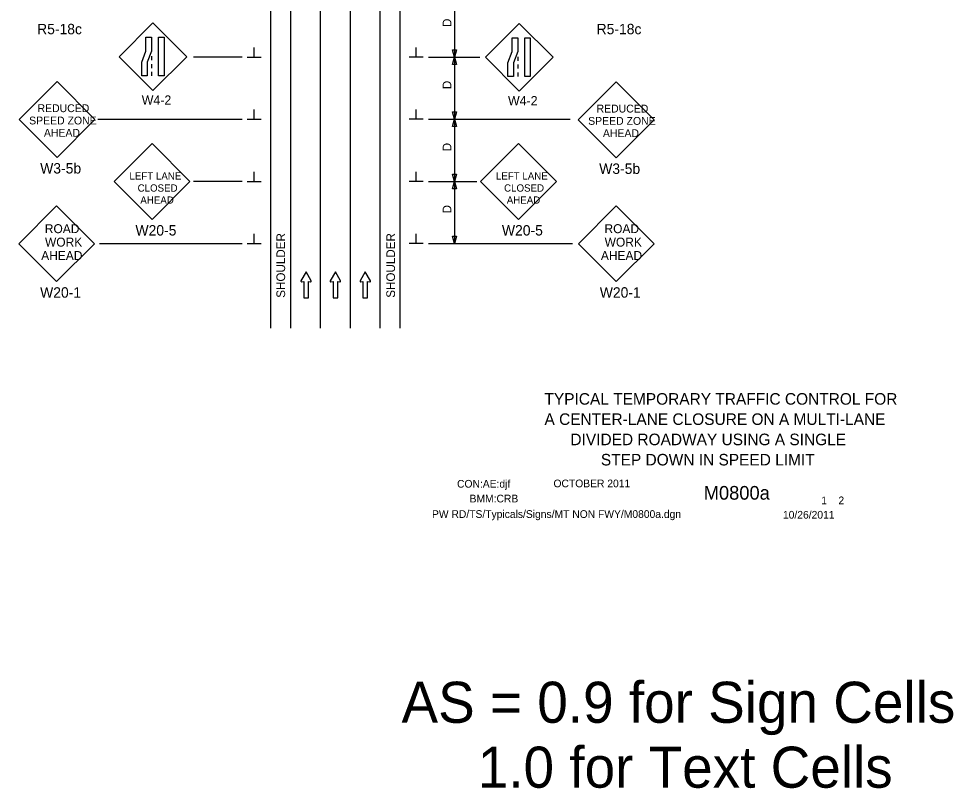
# Model space of a CAD drawing. Extents: x 16732 to 18482, y 5716 to 6919.
# Drawn here: x 16738 to 17490, y 5716 to 6335 of the extents above; entities that cross this region are included whole.
import ezdxf

# ---------------------------------------------------------------- set-up
doc = ezdxf.new("R2010")
doc.units = 0
for name, color, linetype in [('ALI_LEGAL_EX', 7, 'Continuous'), ('BORDER', 7, 'Continuous'), ('BORDER_SIGNAL_WO', 7, 'Continuous'), ('MT_SCRATCH_LEVEL_E', 7, 'Continuous'), ('PAVT_EDGE_EX', 7, 'Continuous'), ('TRAFFIC_SIGNS_PR', 7, 'Continuous'), ('TYPICAL_TEXT_DIMEN_PR', 7, 'Continuous')]:
    doc.layers.add(name, color=color, linetype=linetype)

msp = doc.modelspace()

# ---------------------------------------------------------------- linework, layer by layer
at = {"layer": 'ALI_LEGAL_EX'}
for p, q in [((16980.68, 6904.41), (16980.68, 6086.27)), ((17004.68, 6904.41), (17004.68, 6086.27))]:
    msp.add_line(p, q, dxfattribs=at)
for points in [[(16980.68, 6304.41), (16980.68, 6279.41)], [(17004.68, 6304.41), (17004.68, 6279.41)], [(16980.68, 6204.41), (16980.68, 6179.41)], [(17004.68, 6204.41), (17004.68, 6179.41)], [(16980.68, 6104.41), (16980.68, 6086.27)], [(17004.68, 6104.41), (17004.68, 6086.27)]]:
    msp.add_lwpolyline(points, dxfattribs=at)
at = {"layer": 'MT_SCRATCH_LEVEL_E'}
for p, q in [((16969.24, 6131.56), (16965.12, 6124.32)), ((16973.38, 6124.32), (16969.24, 6131.56)), ((16992.78, 6131.56), (16988.67, 6124.32)), ((16996.93, 6124.32), (16992.78, 6131.56)), ((17016.85, 6131.56), (17012.74, 6124.32)), ((17021, 6124.32), (17016.85, 6131.56)), ((16965.61, 6123.63), (16967.38, 6123.95)), ((16967.38, 6123.95), (16967.38, 6110.69)), ((16971.13, 6110.69), (16971.13, 6123.95)), ((16971.13, 6123.95), (16972.9, 6123.63)), ((16989.15, 6123.63), (16990.93, 6123.95)), ((16990.93, 6123.95), (16990.93, 6110.69)), ((16994.67, 6110.69), (16994.67, 6123.95)), ((16994.67, 6123.95), (16996.45, 6123.63)), ((17013.22, 6123.63), (17015, 6123.95)), ((17015, 6123.95), (17015, 6110.69)), ((17018.74, 6110.69), (17018.74, 6123.95)), ((17018.74, 6123.95), (17020.52, 6123.63)), ((16967.38, 6110.69), (16971.13, 6110.69)), ((16990.93, 6110.69), (16994.67, 6110.69)), ((17015, 6110.69), (17018.74, 6110.69))]:
    msp.add_line(p, q, dxfattribs=at)
for centre, start, end in [((16965.53, 6124.09), 150.42484, 279.96381), ((16972.97, 6124.09), 260.03619, 29.77312), ((16989.08, 6124.09), 150.42484, 279.96381), ((16996.52, 6124.09), 260.03619, 29.77312), ((17013.15, 6124.09), 150.42484, 279.96381), ((17020.59, 6124.09), 260.03619, 29.77312)]:
    msp.add_arc(centre, 0.463, start, end, dxfattribs=at)
at = {"layer": 'PAVT_EDGE_EX'}
for p, q in [((16940.68, 6904.41), (16940.68, 6086.27)), ((16956.68, 6904.41), (16956.68, 6086.27)), ((17028.68, 6904.41), (17028.68, 6086.27)), ((17044.68, 6904.41), (17044.68, 6086.27))]:
    msp.add_line(p, q, dxfattribs=at)
at = {"layer": 'TRAFFIC_SIGNS_PR'}
for p, q in [((16846.05, 6331.9), (16818.89, 6304.75)), ((16873.2, 6304.75), (16846.05, 6331.9)), ((17140.75, 6331.41), (17113.6, 6304.25)), ((17167.91, 6304.25), (17140.75, 6331.41)), ((16818.89, 6304.75), (16846.05, 6277.6)), ((16844.8, 6305.24), (16844.8, 6302.04)), ((16846.05, 6277.6), (16873.2, 6304.75)), ((17113.6, 6304.25), (17140.75, 6277.1)), ((17139.51, 6304.75), (17139.51, 6301.55)), ((17140.75, 6277.1), (17167.91, 6304.25)), ((16844.8, 6298.84), (16844.8, 6295.64)), ((17139.51, 6298.35), (17139.51, 6295.15)), ((16844.8, 6292.44), (16844.8, 6289.24)), ((17139.51, 6291.95), (17139.51, 6288.75)), ((16768.84, 6284.73), (16738.29, 6254.19)), ((16799.38, 6254.19), (16768.84, 6284.73)), ((17218.65, 6284.42), (17188.1, 6253.88)), ((17249.19, 6253.88), (17218.65, 6284.42)), ((16738.29, 6254.19), (16768.84, 6223.64)), ((16768.84, 6223.64), (16799.38, 6254.19)), ((17188.1, 6253.88), (17218.65, 6223.33)), ((17218.65, 6223.33), (17249.19, 6253.88)), ((16845.25, 6234.84), (16814.7, 6204.29)), ((16875.79, 6204.29), (16845.25, 6234.84)), ((17140.11, 6234.84), (17109.56, 6204.29)), ((17170.65, 6204.29), (17140.11, 6234.84)), ((16814.7, 6204.29), (16845.25, 6173.74)), ((16845.25, 6173.74), (16875.79, 6204.29)), ((17109.56, 6204.29), (17140.11, 6173.74)), ((17140.11, 6173.74), (17170.65, 6204.29)), ((16768.53, 6184.86), (16737.99, 6154.32)), ((16799.08, 6154.32), (16768.53, 6184.86)), ((17218.85, 6184.86), (17188.31, 6154.32)), ((17249.4, 6154.32), (17218.85, 6184.86)), ((16737.99, 6154.32), (16768.53, 6123.77)), ((16768.53, 6123.77), (16799.08, 6154.32)), ((17188.31, 6154.32), (17218.85, 6123.77)), ((17218.85, 6123.77), (17249.4, 6154.32))]:
    msp.add_line(p, q, dxfattribs=at)
for points in [[(16844.8, 6320.48), (16844.8, 6309.3), (16841.46, 6300.42), (16841.46, 6289.24), (16836.96, 6289.24), (16836.96, 6300.42), (16840.31, 6309.3), (16840.31, 6320.48)], [(16854.94, 6320.48), (16854.94, 6289.24), (16850.44, 6289.24), (16850.44, 6320.48)], [(17139.51, 6319.99), (17139.51, 6308.81), (17136.16, 6299.93), (17136.16, 6288.75), (17131.67, 6288.75), (17131.67, 6299.93), (17135.01, 6308.81), (17135.01, 6319.99)], [(17149.64, 6319.99), (17149.64, 6288.75), (17145.15, 6288.75), (17145.15, 6319.99)]]:
    msp.add_lwpolyline(points, close=True, dxfattribs=at)
at = {"layer": 'TYPICAL_TEXT_DIMEN_PR'}
for p, q in [((17088.68, 6354.43), (17088.68, 6304.43)), ((16927.55, 6304.43), (16927.55, 6312.21)), ((17057.8, 6304.43), (17057.8, 6312.21)), ((17088.68, 6304.43), (17087.11, 6310.29)), ((17087.11, 6310.29), (17088.68, 6310.29)), ((17088.68, 6310.29), (17090.25, 6310.29)), ((17090.25, 6310.29), (17088.68, 6304.43)), ((16917.68, 6304.43), (16878.68, 6304.43)), ((16921.93, 6304.43), (16933.18, 6304.43)), ((17063.43, 6304.43), (17052.18, 6304.43)), ((17067.68, 6304.43), (17109.12, 6304.43)), ((17087.11, 6298.57), (17088.68, 6304.43)), ((17088.68, 6304.43), (17088.68, 6254.43)), ((17088.68, 6304.43), (17090.25, 6298.57)), ((17088.68, 6298.57), (17087.11, 6298.57)), ((17090.25, 6298.57), (17088.68, 6298.57)), ((16927.55, 6254.43), (16927.55, 6262.21)), ((17057.8, 6254.43), (17057.8, 6262.21)), ((17088.68, 6254.43), (17087.11, 6260.29)), ((17087.11, 6260.29), (17088.68, 6260.29)), ((17088.68, 6260.29), (17090.25, 6260.29)), ((17090.25, 6260.29), (17088.68, 6254.43)), ((16801.71, 6254.43), (16917.68, 6254.43)), ((16921.93, 6254.43), (16933.18, 6254.43)), ((17063.43, 6254.43), (17052.18, 6254.43)), ((17067.68, 6254.43), (17181.75, 6254.43)), ((17087.11, 6248.57), (17088.68, 6254.43)), ((17088.68, 6254.43), (17088.68, 6204.43)), ((17088.68, 6254.43), (17090.25, 6248.57)), ((17088.68, 6248.57), (17087.11, 6248.57)), ((17090.25, 6248.57), (17088.68, 6248.57)), ((16927.55, 6204.43), (16927.55, 6212.21)), ((17057.8, 6204.43), (17057.8, 6212.21)), ((16917.68, 6204.43), (16878.68, 6204.43)), ((16921.93, 6204.43), (16933.18, 6204.43)), ((17063.43, 6204.43), (17052.18, 6204.43)), ((17067.68, 6204.43), (17106.68, 6204.43)), ((17088.68, 6204.43), (17087.11, 6210.29)), ((17087.11, 6210.29), (17088.68, 6210.29)), ((17087.11, 6198.57), (17088.68, 6204.43)), ((17088.68, 6210.29), (17090.25, 6210.29)), ((17090.25, 6210.29), (17088.68, 6204.43)), ((17088.68, 6204.43), (17088.68, 6154.43)), ((17088.68, 6204.43), (17090.25, 6198.57)), ((17088.68, 6198.57), (17087.11, 6198.57)), ((17090.25, 6198.57), (17088.68, 6198.57)), ((16927.55, 6154.43), (16927.55, 6162.21)), ((17057.8, 6154.43), (17057.8, 6162.21)), ((17088.68, 6154.43), (17087.11, 6160.29)), ((17087.11, 6160.29), (17088.68, 6160.29)), ((17088.68, 6160.29), (17090.25, 6160.29)), ((17090.25, 6160.29), (17088.68, 6154.43)), ((16802.89, 6154.43), (16917.68, 6154.43)), ((16921.93, 6154.43), (16933.18, 6154.43)), ((17063.43, 6154.43), (17052.18, 6154.43)), ((17067.68, 6154.43), (17183.65, 6154.43))]:
    msp.add_line(p, q, dxfattribs=at)

# ---------------------------------------------------------------- texts
at = {"layer": 'BORDER'}
for s, p in [('TYPICAL TEMPORARY TRAFFIC CONTROL FOR', (17161.04, 6024.8)), ('A CENTER-LANE CLOSURE ON A MULTI-LANE', (17161.06, 6008.5)), ('DIVIDED ROADWAY USING A SINGLE ', (17181.92, 5992.2)), ('STEP DOWN IN SPEED LIMIT', (17206.42, 5975.9))]:
    msp.add_text(s, height=9.3, dxfattribs=at).set_placement(p)
at = {"layer": 'BORDER_SIGNAL_WO'}
for s, height, p in [('CON:AE:djf', 6.2, (17090.69, 5958.06)), ('    OCTOBER 2011    ', 6.2, (17159.08, 5958.34)), ('    M0800a   ', 11, (17272.86, 5948.38)), ('BMM:CRB   ', 6.2, (17100.81, 5946.17)), (' 1    2 ', 6.2, (17381.45, 5944.7)), ('PW RD/TS/Typicals/Signs/MT NON FWY/M0800a.dgn    ', 6.2, (17070.55, 5933.71)), ('10/26/2011    ', 6.2, (17352.93, 5933.13)), ('AS = 0.9 for Sign Cells', 33.0301, (17046.01, 5768.88)), ('     1.0 for Text Cells', 33.0301, (17046.01, 5716.65))]:
    msp.add_text(s, height=height, dxfattribs=at).set_placement(p)
at = {"layer": 'TRAFFIC_SIGNS_PR'}
for s, height, p in [('R5-18c', 8.37, (16752.8, 6322.81)), ('R5-18c', 8.37, (17202.99, 6322.81)), ('W4-2', 7.44, (16837, 6266.16)), ('W4-2', 7.44, (17131.71, 6265.66)), ('REDUCED', 6.3, (16753.15, 6260.16)), ('REDUCED', 6.3, (17202.96, 6259.85)), ('SPEED ZONE', 6.3, (16746.39, 6250.26)), ('SPEED ZONE', 6.3, (17196.2, 6249.95)), ('AHEAD', 6.3, (16758.27, 6240.36)), ('AHEAD', 6.3, (17208.08, 6240.05)), ('W3-5b', 8.37, (16755.28, 6210.77)), ('W3-5b', 8.37, (17205.09, 6210.46)), ('LEFT LANE', 5.85, (16827.11, 6205.86)), ('LEFT LANE', 5.85, (17121.97, 6205.86)), ('CLOSED', 5.85, (16833.67, 6196.19)), ('CLOSED', 5.85, (17128.53, 6196.19)), ('AHEAD', 5.85, (16835.86, 6186.51)), ('AHEAD', 5.85, (17130.72, 6186.51)), ('ROAD', 7.2, (16759.02, 6162.79)), ('W20-5', 8.37, (16831.94, 6160.88)), ('W20-5', 8.37, (17126.8, 6160.88)), ('ROAD', 7.2, (17209.34, 6162.79)), ('WORK', 7.2, (16759.14, 6151.99)), ('WORK', 7.2, (17209.46, 6151.99)), ('AHEAD', 7.2, (16756.11, 6141.19)), ('AHEAD', 7.2, (17206.43, 6141.19)), ('W20-1', 8.37, (16755.22, 6110.9)), ('W20-1', 8.37, (17205.54, 6110.9))]:
    msp.add_text(s, height=height, dxfattribs=at).set_placement(p)
at = {"layer": 'TYPICAL_TEXT_DIMEN_PR'}
for s, p in [('D', (17086.12, 6328.65)), ('D', (17086.12, 6278.65)), ('D', (17086.12, 6228.65)), ('D', (17086.12, 6178.65)), ('SHOULDER', (16952.36, 6110.81)), ('SHOULDER', (17040.79, 6110.81))]:
    msp.add_text(s, height=7, rotation=90, dxfattribs=at).set_placement(p)

doc.saveas('drawing.dxf')
